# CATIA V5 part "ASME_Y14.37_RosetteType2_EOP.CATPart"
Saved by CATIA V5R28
Part number: 333X3333-303
Revision: --
Nomenclature: ASME_Y14.37_RosetteType2
Bounding box of the stored display mesh (mm): x -188.298 to 149.059, y -714.612 to 664.697, z 0 to 91.639
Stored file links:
  C:\Users\jvl2147\Documents\AP242 testing\Composite Example Parts for PER\EOP\ASME_Y14.37_RosetteType2_EOP.CATPart
  \\NW\Data\MSE-Composites\ASME Y14.37\ASME Y-14.37_COMPOSITES.CATMaterial
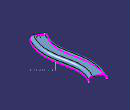
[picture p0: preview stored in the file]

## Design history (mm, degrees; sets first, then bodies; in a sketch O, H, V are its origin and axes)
AxisSystem1 "ROSETTE COORDINATE SYSTEM": origin (-72.9205, -637.9645, 93.98), X (0.5026, 0.8645, 0), Y (-0.8645, 0.5026, 0), Z (0, 0, 1)
CompParametersFeature1 "CATCoParametersFeatName": Value 0, Value 45, Value -45, Value 90
CompEOPGroupFeature1 "CATCoEOPGroupFeatName"
CompStacking1 "Stacking"
CompIsoThickAreasGroup1 "CATCoIsoThickAreasGroupFeatName": RefAddThickness 0
TTRSSet1
f4a2d38f3ddc11d3a929006094b99c4b_11 "CATTPSSet"
CompReviewTools1 "Review tools"
Set1 "CONSTRUCTION GEOMETRY"
  Set2 "CONSTRUCTION - LAMINATE REFERENCE SURFACE"
    Sketch1 on xy-plane, origin (0, 0, 0), H (1, 0, 0), V (0, 1, 0)
      spline S1 through (-79.505, -649.09) (21.2912, -260.3998) (-51.6257, 228.8061) (37.963, 602.845)
    Plane1: type Normal, Curve Sketch1, RefPoint vertex of Sketch1, Ratio 0
    Sketch2 on Plane1, origin (-464.3095, -417.3341, 0), H (-0.8566, 0.5159, 0), V (0, 0, 1)
      line L1 (-525.4052, 91.6386) -> (-373.0052, 91.6386)
      line L2 (-322.2052, 40.8386) -> (-322.2052, 0)
      line L3 (-576.2052, 0) -> (-576.2052, 40.8386)
      reference projected point E1 (-449.2052, 0) from vertex of Sketch1
      reference projected point E2 (-449.2052, 0) from vertex of Sketch1
      arc A1 centre (-373.0052, 40.8386) radius 50.8 from (-373.0052, 91.6386) to (-322.2052, 40.8386) cw
      arc A2 centre (-525.4052, 40.8386) radius 50.8 from (-576.2052, 40.8386) to (-525.4052, 91.6386) cw
      distance E1 L2 = 127
      distance E2 L3 = 127
      radius A1 = 50.8
      radius A2 = 50.8
      horizontal: L1 H
      vertical: L2 V, L3 V
      tangency: A1 L1, A1 L2, A2 L3, A2 L1
    Sweep1: type Unspec, Profile Sketch2, Guide Sketch1
  Set3 "CONSTRUCTION - PLIES EOPS"
    Plane2: type Normal, Curve Sketch1, RefPoint vertex of Sketch1, Ratio 0
    Plane3: type Normal, Curve Sketch1, RefPoint {point type OnCurve, Support Sketch1, Length 1118.262}, Ratio 0.99
    Plane4: type Normal, Curve Sketch1, Ratio 0.01
    Intersect1: ToIntersect1 Plane3, ToIntersect2 Sweep1
    Intersect2: ToIntersect1 Sweep1, ToIntersect2 Plane4
    Plane5: type Offset, RefPlane xy-plane, Offset 2.54
    Intersect3: ToIntersect1 Plane5, ToIntersect2 Join1
    Near1: MultiElement Intersect3, ReferenceElement edge of Sweep1
    Near2: MultiElement Intersect3, ReferenceElement edge of Sweep1
  Set4 "CONSTRUCTION - ROSETTE COORDINATE SYSTEM"
    Intersect4: ToIntersect1 Plane4, ToIntersect2 Project2
    Line1: type Tangency, RefPoint Intersect4, Curve Project2, Start 0, End 25.4
    Plane6: type Offset, RefPlane xy-plane, Offset 93.98
    Project1 "PROJECT": ToProject Sketch1, Support Join1, Direction xy-plane
  Set5 "CONSTRUCTION - ROSETTE TRANSFORMS"
    Line2 "Ply.1_Rosette_transfer_X": type Tangency, RefPoint {point type OnCurve, Support Project2, Length 288.56}, Curve Project2, Support Join1, Start 0, End 25.4
    Line3 "Ply.1_Rosette_transfer_X.Renamed": type Tangency, RefPoint {point type OnCurve, Support Project2, Length 536.186}, Curve Project2, Support Join1, Start 25.4, End 0
    Line4 "Ply.1_Rosette_transfer_X.Renamed": type Tangency, RefPoint {point type OnCurve, Support Project2, Length 783.62}, Curve Project2, Support Join1, Start 25.4, End 0
    Line5 "Ply.1_Rosette_transfer_X.Renamed": type Tangency, RefPoint {point type OnCurve, Support Project2, Length 1274.71}, Curve Project2, Support Join1, Start 25.4, End 0
    Line6 "Ply.1_Rosette_transfer_X.Renamed": type Tangency, RefPoint {point type OnCurve, Support Project2, Length 1017.245}, Curve Project2, Support Join1, Start 25.4, End 0
    AxisSystem2 "ROSETTE COORDINATE SYSTEM": origin (16.8931, -379.3831, 93.98), X (0.1242, 0.9923, 0), Y (-0.9923, 0.1242, 0), Z (0, 0, 1)
    AxisSystem3 "ROSETTE COORDINATE SYSTEM.Renamed": origin (7.1166, -132.8437, 93.98), X (-0.1632, 0.9866, 0), Y (-0.9866, -0.1632, 0), Z (0, 0, 1)
    AxisSystem4 "ROSETTE COORDINATE SYSTEM.Renamed1": origin (-38.9217, 110.2518, 93.98), X (-0.1571, 0.9876, 0), Y (-0.9876, -0.1571, 0), Z (0, 0, 1)
    AxisSystem5 "ROSETTE COORDINATE SYSTEM.Renamed2": origin (29.3229, 586.9432, 93.98), X (0.4677, 0.8839, 0), Y (-0.8839, 0.4677, 0), Z (0, 0, 1)
    AxisSystem6 "ROSETTE COORDINATE SYSTEM.Renamed3": origin (-47.995, 342.9553, 93.98), X (0.1137, 0.9935, 0), Y (-0.9935, 0.1137, 0), Z (0, 0, 1)
    Point1: type OnSurface, Support Join1, Length 362.156, Direction (-0.4364, -0.3881, 0.8118)
    Line7: type Normal, RefPoint Point1, RefSkin Join1, Start 254, End 0
  Plane7: type Offset, RefPlane YZ plane of AxisSystem2, Offset 0
  Circle1: type CtrRad, Start 0, End 180, Center {point type OnSurface, Support Join1, Length 336.531, Direction (0.5738, 0.5102, 0.6407)}, Support Join1, Radius 50.8, FirstDirection (1, 0, 0)
  CurvePar1: Offset Near1, Support Join1, Offset2 0, Offset1 50.8
Set6 "ENGINEERING GEOMETRY"
  Set7 "LAMINATE REFERENCE SURFACE"
    Join1 "LAMINATE REFERENCE SURFACE": Elements Sweep1
  Set8 "GUIDE CURVE - ZERO DEGREE ORIENTATION"
    Project2 "GUIDE CURVE - 0°": ToProject Sketch1, Support Plane6
Body1 (main body)
Body2 "-303"
  CompIsoThickAreasSolid1 "Area Solid.1": IsoAreasGroup CompIsoThickAreasGroup1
